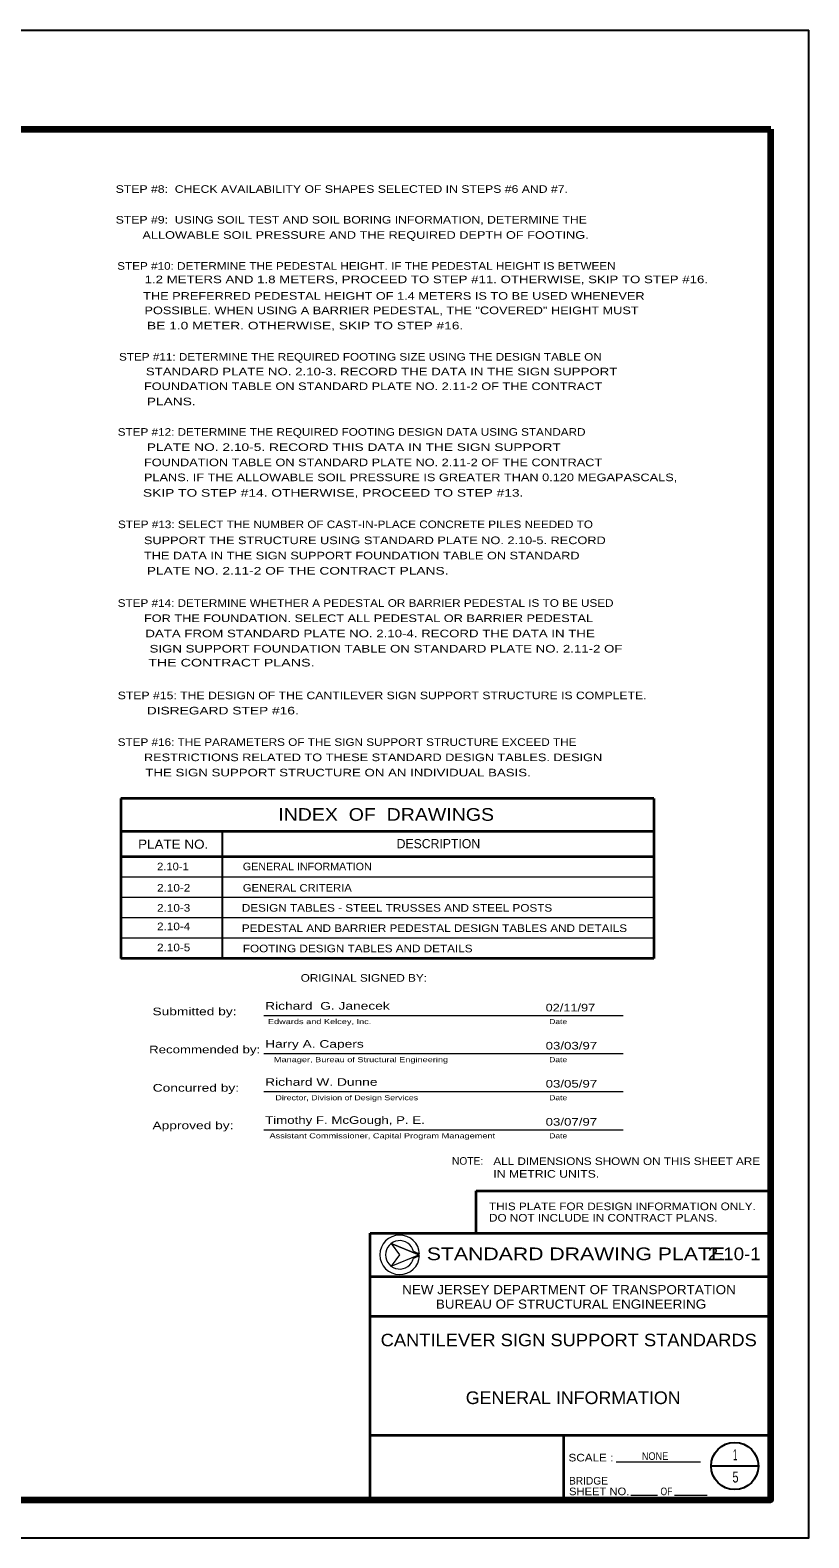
# Model space of a CAD drawing. Extents: x 312601.858 to 312602.699, y 144420.109 to 144420.704.
# Drawn here: x 312602.392 to 312602.699, y 144420.109 to 144420.704 of the extents above; entities that cross this region are included whole.
import ezdxf
from ezdxf.enums import TextEntityAlignment as Align

# ---------------------------------------------------------------- set-up
doc = ezdxf.new("R2010")
doc.units = 0
doc.header["$LTSCALE"] = 0.0012
for name, color, linetype, lineweight in [('1', 7, 'Continuous', 25), ('2', 7, 'Continuous', 25), ('39', 7, 'Continuous', 25)]:
    doc.layers.add(name, color=color, linetype=linetype, lineweight=lineweight)
doc.layers.add('4', color=7, linetype='Continuous')
doc.layers.add('51', color=7, linetype='Continuous')

msp = doc.modelspace()

# ---------------------------------------------------------------- linework, layer by layer
at = {"layer": '1', "lineweight": 35}
for p, q in [((312602.4277, 144420.4008), (312602.4277, 144420.3378)), ((312602.6377, 144420.4008), (312602.4277, 144420.4008)), ((312602.6377, 144420.4008), (312602.6377, 144420.3378)), ((312602.6377, 144420.3878), (312602.4277, 144420.3878)), ((312602.6377, 144420.3778), (312602.4277, 144420.3778)), ((312602.6377, 144420.3378), (312602.4277, 144420.3378))]:
    msp.add_line(p, q, dxfattribs=at)
at = {"layer": '1'}
msp.add_line((312602.4677, 144420.3878), (312602.4677, 144420.3378), dxfattribs=at)
at = {"layer": '1', "lineweight": 13}
for p, q in [((312602.6377, 144420.3698), (312602.4277, 144420.3698)), ((312602.6377, 144420.3618), (312602.4277, 144420.3618)), ((312602.6377, 144420.3538), (312602.4277, 144420.3538)), ((312602.6377, 144420.3458), (312602.4277, 144420.3458)), ((312602.4841, 144420.3153), (312602.6256, 144420.3153)), ((312602.4841, 144420.3003), (312602.6256, 144420.3003)), ((312602.4841, 144420.2853), (312602.6256, 144420.2853)), ((312602.4841, 144420.2703), (312602.6256, 144420.2703)), ((312602.5431, 144420.2197), (312602.5454, 144420.2207)), ((312602.6286, 144420.1263), (312602.6392, 144420.1263)), ((312602.6459, 144420.1263), (312602.6587, 144420.1263))]:
    msp.add_line(p, q, dxfattribs=at)
for points in [[(312602.5452, 144420.221), (312602.5343, 144420.2255), (312602.5452, 144420.221)], [(312602.5454, 144420.2213), (312602.5431, 144420.2223), (312602.543, 144420.2223)]]:
    msp.add_lwpolyline(points, dxfattribs=at)
for points in [[(312602.5452, 144420.221), (312602.5343, 144420.2255), (312602.5375, 144420.221), (312602.5343, 144420.2165)], [(312602.5375, 144420.221), (312602.5343, 144420.2165), (312602.5452, 144420.221), (312602.5343, 144420.2255)]]:
    msp.add_lwpolyline(points, close=True, dxfattribs=at)
for radius, start, end in [(0.0078, 2.21392, 357.78608), (0.0056, 13.69411, 346.30589)]:
    msp.add_arc((312602.5376, 144420.221), radius, start, end, dxfattribs=at)
at = {"layer": '39'}
for p, q in [((312601.8578, 144420.7035), (312602.6988, 144420.7035)), ((312602.6988, 144420.1095), (312602.6988, 144420.7035)), ((312602.6988, 144420.1095), (312602.6988, 144420.7035)), ((312602.5735, 144420.6645), (312602.6838, 144420.6645)), ((312602.6838, 144420.6514), (312602.6838, 144420.6645)), ((312602.6789, 144420.1378), (312602.6603, 144420.1378)), ((312602.452, 144420.1245), (312602.6838, 144420.1245)), ((312601.8578, 144420.1095), (312602.6988, 144420.1095)), ((312601.8578, 144420.1095), (312602.6988, 144420.1095))]:
    msp.add_line(p, q, dxfattribs=at)
at = {"layer": '39', "lineweight": 158}
for p, q in [((312601.9088, 144420.6645), (312602.6838, 144420.6645)), ((312602.6838, 144420.1247), (312602.6838, 144420.6645)), ((312602.6838, 144420.1247), (312602.6838, 144420.6645)), ((312601.9088, 144420.1245), (312602.6838, 144420.1245)), ((312601.9088, 144420.1245), (312602.6838, 144420.1245))]:
    msp.add_line(p, q, dxfattribs=at)
at = {"layer": '39', "lineweight": 35}
for p, q in [((312602.5677, 144420.2462), (312602.6838, 144420.2462)), ((312602.5677, 144420.2295), (312602.5677, 144420.2462)), ((312602.526, 144420.1245), (312602.526, 144420.2295)), ((312602.526, 144420.2295), (312602.6838, 144420.2295)), ((312602.6838, 144420.2295), (312602.6838, 144420.1245)), ((312602.526, 144420.2124), (312602.6838, 144420.2124)), ((312602.526, 144420.1968), (312602.6838, 144420.1968)), ((312602.526, 144420.1499), (312602.6838, 144420.1499)), ((312602.6022, 144420.1248), (312602.6022, 144420.1499))]:
    msp.add_line(p, q, dxfattribs=at)
at = {"layer": '39', "lineweight": 13}
for p, q in [((312602.6022, 144420.1499), (312602.6838, 144420.1499)), ((312602.6229, 144420.1395), (312602.6561, 144420.1395))]:
    msp.add_line(p, q, dxfattribs=at)
at = {"layer": '39'}
msp.add_lwpolyline([(312601.8578, 144420.1095), (312602.6988, 144420.1095), (312602.6988, 144420.7035)], dxfattribs=at)
at = {"layer": '39', "lineweight": 158}
msp.add_lwpolyline([(312601.9088, 144420.1245), (312602.6838, 144420.1245), (312602.6838, 144420.6645)], dxfattribs=at)
at = {"layer": '39', "lineweight": 13}
msp.add_lwpolyline([(312602.5452, 144420.221), (312602.5343, 144420.2255), (312602.5375, 144420.221), (312602.5343, 144420.2165)], close=True, dxfattribs=at)
at = {"layer": '39'}
msp.add_circle((312602.6696, 144420.1378), 0.0093, dxfattribs=at)

# ---------------------------------------------------------------- texts
at = {"layer": '1'}
for s, width, p in [('STEP #8:  CHECK AVAILABILITY OF SHAPES SELECTED IN STEPS #6 AND #7.', 1.2, (312602.4257, 144420.6394)), ('STEP #9:  USING SOIL TEST AND SOIL BORING INFORMATION, DETERMINE THE', 1.2, (312602.4257, 144420.6273)), ('          ALLOWABLE SOIL PRESSURE AND THE REQUIRED DEPTH OF FOOTING.', 1.25, (312602.4223, 144420.6213)), ('STEP #10: DETERMINE THE PEDESTAL HEIGHT. IF THE PEDESTAL HEIGHT IS BETWEEN', 1.15, (312602.4263, 144420.6091)), ('          1.2 METERS AND 1.8 METERS, PROCEED TO STEP #11. OTHERWISE, SKIP TO STEP #16. ', 1.3, (312602.4226, 144420.6038)), ('          THE PREFERRED PEDESTAL HEIGHT OF 1.4 METERS IS TO BE USED WHENEVER', 1.25, (312602.4226, 144420.5973)), ('          POSSIBLE. WHEN USING A BARRIER PEDESTAL, THE "COVERED" HEIGHT MUST', 1.25, (312602.4231, 144420.5916)), ('          BE 1.0 METER. OTHERWISE, SKIP TO STEP #16.', 1.35, (312602.423, 144420.5856)), ('STEP #11: DETERMINE THE REQUIRED FOOTING SIZE USING THE DESIGN TABLE ON', 1.15, (312602.427, 144420.5733)), ('          STANDARD PLATE NO. 2.10-3. RECORD THE DATA IN THE SIGN SUPPORT', 1.3, (312602.4231, 144420.5675)), ('          FOUNDATION TABLE ON STANDARD PLATE NO. 2.11-2 OF THE CONTRACT', 1.25, (312602.4229, 144420.5617)), ('          PLANS.', 1.35, (312602.4229, 144420.5557)), ('STEP #12: DETERMINE THE REQUIRED FOOTING DESIGN DATA USING STANDARD', 1.15, (312602.4265, 144420.5437)), ('          PLATE NO. 2.10-5. RECORD THIS DATA IN THE SIGN SUPPORT', 1.35, (312602.4229, 144420.5377)), ('          FOUNDATION TABLE ON STANDARD PLATE NO. 2.11-2 OF THE CONTRACT', 1.25, (312602.4229, 144420.5317)), ('          PLANS. IF THE ALLOWABLE SOIL PRESSURE IS GREATER THAN 0.120 MEGAPASCALS,', 1.25, (312602.4229, 144420.5258)), ('           SKIP TO STEP #14. OTHERWISE, PROCEED TO STEP #13.', 1.35, (312602.4199, 144420.5197)), ('STEP #13: SELECT THE NUMBER OF CAST-IN-PLACE CONCRETE PILES NEEDED TO', 1.15, (312602.4266, 144420.5073)), ('          SUPPORT THE STRUCTURE USING STANDARD PLATE NO. 2.10-5. RECORD', 1.25, (312602.4229, 144420.501)), ('          THE DATA IN THE SIGN SUPPORT FOUNDATION TABLE ON STANDARD', 1.25, (312602.4229, 144420.495)), ('          PLATE NO. 2.11-2 OF THE CONTRACT PLANS.', 1.35, (312602.4229, 144420.489)), ('STEP #14: DETERMINE WHETHER A PEDESTAL OR BARRIER PEDESTAL IS TO BE USED', 1.15, (312602.4265, 144420.4763)), ('          FOR THE FOUNDATION. SELECT ALL PEDESTAL OR BARRIER PEDESTAL', 1.25, (312602.4229, 144420.4703)), ('          DATA FROM STANDARD PLATE NO. 2.10-4. RECORD THE DATA IN THE ', 1.3, (312602.4229, 144420.4643)), ('          THE CONTRACT PLANS.', 1.4, (312602.4229, 144420.4528)), ('         SIGN SUPPORT FOUNDATION TABLE ON STANDARD PLATE NO. 2.11-2 OF ', 1.3, (312602.426, 144420.4583)), ('STEP #15: THE DESIGN OF THE CANTILEVER SIGN SUPPORT STRUCTURE IS COMPLETE. ', 1.2, (312602.4265, 144420.4399)), ('          DISREGARD STEP #16.', 1.35, (312602.4229, 144420.4339)), ('STEP #16: THE PARAMETERS OF THE SIGN SUPPORT STRUCTURE EXCEED THE', 1.15, (312602.4265, 144420.4215)), ('          RESTRICTIONS RELATED TO THESE STANDARD DESIGN TABLES. DESIGN', 1.25, (312602.4229, 144420.4155)), ('          THE SIGN SUPPORT STRUCTURE ON AN INDIVIDUAL BASIS.', 1.3, (312602.4229, 144420.4095)), ('2.10-1', 1.1, (312602.442, 144420.3725)), ('GENERAL INFORMATION', 1.05, (312602.4758, 144420.3725)), ('2.10-2', 1.15, (312602.442, 144420.3641)), ('GENERAL CRITERIA', 1.1, (312602.4758, 144420.3641)), ('2.10-3', 1.15, (312602.442, 144420.3562)), ('DESIGN TABLES - STEEL TRUSSES AND STEEL POSTS', 1.15, (312602.4754, 144420.3562)), ('2.10-4', 1.15, (312602.442, 144420.3489)), ('PEDESTAL AND BARRIER PEDESTAL DESIGN TABLES AND DETAILS', 1.15, (312602.4754, 144420.3482)), ('2.10-5', 1.15, (312602.442, 144420.3406)), ('FOOTING DESIGN TABLES AND DETAILS', 1.15, (312602.4758, 144420.3402))]:
    msp.add_text(s, height=0.003, dxfattribs=dict(at, width=width)).set_placement(p)
for s, height, width, p in [('INDEX  OF  DRAWINGS', 0.005, 1.15, (312602.53225, 144420.392)), ('PLATE NO.', 0.0036, 1.1, (312602.44835, 144420.381)), ('NONE', 0.003, 0.9, (312602.6382, 144420.1402))]:
    msp.add_text(s, height=height, dxfattribs=dict(at, width=width)).set_placement(p, align=Align.CENTER)
msp.add_text('DESCRIPTION', height=0.0036, dxfattribs=at).set_placement((312602.55285, 144420.3812), align=Align.CENTER)
at = {"layer": '2'}
for s, height, width, p in [('Submitted by:', 0.003, 1.35, (312602.45675, 144420.3154)), ('Edwards and Kelcey, Inc.', 0.002, 1.35, (312602.50605, 144420.3119)), ('Date', 0.002, 1.25, (312602.60005, 144420.3119)), ('Recommended by:', 0.003, 1.3, (312602.46075, 144420.3004)), ('Manager, Bureau of Structural Engineering', 0.002, 1.35, (312602.52235, 144420.2969)), ('Date', 0.002, 1.25, (312602.60005, 144420.2969)), ('Concurred by:', 0.003, 1.35, (312602.4573, 144420.2853)), ('Director, Division of Design Services', 0.002, 1.3, (312602.51675, 144420.2819)), ('Date', 0.002, 1.25, (312602.60005, 144420.2819)), ('Approved by:', 0.003, 1.35, (312602.45615, 144420.2705)), ('Assistant Commissioner, Capital Program Management', 0.002, 1.35, (312602.53075, 144420.2669)), ('Date', 0.002, 1.25, (312602.60005, 144420.2669)), ('2.10-1', 0.005, 1.1, (312602.6694, 144420.2189)), ('CANTILEVER SIGN SUPPORT STANDARDS', 0.0049, 1.1, (312602.6042, 144420.185)), ('GENERAL INFORMATION', 0.005, 1.05, (312602.60595, 144420.1622))]:
    msp.add_text(s, height=height, dxfattribs=dict(at, width=width)).set_placement(p, align=Align.CENTER)
at = {"layer": '2', "width": 1.15}
for s, p in [('THIS PLATE FOR DESIGN INFORMATION ONLY.', (312602.5728, 144420.2386)), ('DO NOT INCLUDE IN CONTRACT PLANS.', (312602.5728, 144420.2341))]:
    msp.add_text(s, height=0.003, dxfattribs=at).set_placement(p)
at = {"layer": '39'}
for s, height, width, p in [('STANDARD DRAWING PLATE       ', 0.005, 1.25, (312602.61515, 144420.2189)), ('NEW JERSEY DEPARTMENT OF TRANSPORTATION', 0.003599, 1.1, (312602.6043, 144420.2055)), ('BUREAU OF STRUCTURAL ENGINEERING', 0.0036, 1.1, (312602.6051, 144420.1998)), ('SCALE :', 0.003, 1.15, (312602.61295, 144420.1396)), ('OF', 0.003, 0.85, (312602.6427, 144420.1263))]:
    msp.add_text(s, height=height, dxfattribs=dict(at, width=width)).set_placement(p, align=Align.CENTER)
at = {"layer": '39', "width": 1.1}
msp.add_text('SHEET NO.', height=0.003, dxfattribs=at).set_placement((312602.6043, 144420.1263))
at = {"layer": '39'}
msp.add_text('BRIDGE', height=0.003, dxfattribs=at).set_placement((312602.6043, 144420.1305))
at = {"layer": '4'}
for s, width, p in [('ORIGINAL SIGNED BY:', 1.15, (312602.4986, 144420.3286)), ('Richard  G. Janecek', 1.35, (312602.4846, 144420.3176)), ('02/11/97', 1.25, (312602.5951, 144420.3169)), ('Harry A. Capers', 1.35, (312602.4846, 144420.3026)), ('03/03/97', 1.3, (312602.5951, 144420.3019)), ('Richard W. Dunne', 1.35, (312602.4846, 144420.2876)), ('03/05/97', 1.3, (312602.5951, 144420.2869)), ('Timothy F. McGough, P. E.', 1.3, (312602.4846, 144420.2726)), ('03/07/97', 1.3, (312602.5951, 144420.2719)), ('ALL DIMENSIONS SHOWN ON THIS SHEET ARE', 1.15, (312602.5745, 144420.2564)), ('IN METRIC UNITS.', 1.2, (312602.5745, 144420.2514))]:
    msp.add_text(s, height=0.003, dxfattribs=dict(at, width=width)).set_placement(p)
msp.add_text('NOTE:', height=0.003, dxfattribs=at).set_placement((312602.5582, 144420.2565))
at = {"layer": '51'}
for s, width, p in [('1', 0.45, (312602.66975, 144420.1401)), ('5', 0.75, (312602.6699, 144420.1313))]:
    msp.add_text(s, height=0.0043, dxfattribs=dict(at, width=width)).set_placement(p, align=Align.CENTER)

doc.saveas('drawing.dxf')
